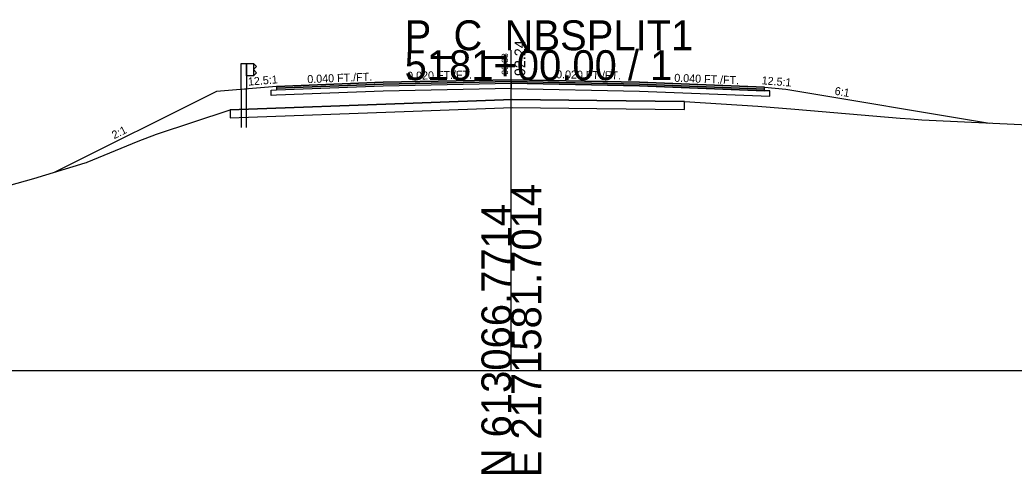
# Model space of a CAD drawing. Extents: x -26 to 1303, y -3010 to 12038.
# Drawn here: x 103.9 to 197.1, y 3990.3 to 4032.8 of the extents above; entities that cross this region are included whole.
import ezdxf

# ---------------------------------------------------------------- set-up
doc = ezdxf.new("R2010")
doc.units = 0
for name, color, linetype in [('RD_GPK_XS_Cell', 7, 'Continuous'), ('RD_PD_Final_TrvlWay', 7, 'Continuous'), ('RD_XS_Base', 7, 'Continuous'), ('RD_XS_ExGround', 7, 'Continuous'), ('RD_XS_ExPaveRet', 7, 'Continuous'), ('RD_XS_GR', 7, 'Continuous'), ('RD_XS_Greenside', 7, 'Continuous'), ('RD_XS_Pave', 7, 'Continuous'), ('RD_XS_PaveOvlay_CP', 7, 'Continuous'), ('RD_XS_TieSlope', 7, 'Continuous'), ('RD_XS_TX_Elev_EX', 7, 'Continuous'), ('RD_XS_TX_Elev_PR', 7, 'Continuous'), ('RD_XS_TX_ShdSlope', 7, 'Continuous'), ('RD_XS_TX_Slope', 7, 'Continuous')]:
    doc.layers.add(name, color=color, linetype=linetype)

msp = doc.modelspace()

# ---------------------------------------------------------------- linework, layer by layer
at = {"layer": 'RD_GPK_XS_Cell'}
for p, q in [((150, 4000), (150, 4030)), ((0, 4000), (150, 4000)), ((150, 4000), (300, 4000))]:
    msp.add_line(p, q, dxfattribs=at)
at = {"layer": 'RD_PD_Final_TrvlWay'}
for p, q in [((125.167, 4026.37), (124.667, 4026.33)), ((124.667, 4026.33), (124.667, 4022.765)), ((125.167, 4022.765), (125.167, 4026.37))]:
    msp.add_line(p, q, dxfattribs=at)
at = {"layer": 'RD_XS_Base'}
for p, q in [((127.5, 4026.259), (128, 4026.279)), ((127.5, 4025.759), (127.5, 4026.259)), ((127.5, 4026.259), (127.5, 4026.259)), ((128, 4026.279), (138, 4026.679)), ((128, 4026.279), (128, 4026.279)), ((138, 4026.679), (150, 4026.919)), ((138, 4026.679), (138, 4026.679)), ((150, 4026.419), (138, 4026.179)), ((150, 4026.919), (150, 4027.078)), ((150, 4027.078), (150, 4026.419)), ((150, 4026.919), (150, 4026.419)), ((162, 4026.679), (150, 4026.919)), ((150, 4026.919), (150, 4026.919)), ((150, 4026.419), (150, 4026.419)), ((150, 4026.419), (150, 4026.419)), ((150, 4026.419), (162, 4026.179)), ((173.73, 4026.21), (162, 4026.679)), ((164, 4026.599), (164, 4026.599)), ((128, 4025.779), (127.5, 4025.759)), ((127.5, 4025.759), (127.5, 4025.759)), ((127.5, 4025.759), (127.5, 4025.759)), ((138, 4026.179), (128, 4025.779)), ((128, 4025.779), (128, 4025.779)), ((138, 4026.179), (138, 4026.179)), ((162, 4026.179), (174.23, 4025.69)), ((164, 4026.099), (164, 4026.099)), ((174.23, 4026.19), (173.73, 4026.21)), ((173.73, 4026.21), (173.73, 4026.21)), ((174.23, 4025.69), (174.23, 4026.19)), ((174.23, 4026.19), (174.23, 4026.19)), ((174.23, 4025.69), (174.23, 4025.69)), ((174.23, 4025.69), (174.23, 4025.69))]:
    msp.add_line(p, q, dxfattribs=at)
at = {"layer": 'RD_XS_ExGround'}
msp.add_lwpolyline([(99.745, 4016.465), (105.253, 4017.976), (110.058, 4019.449), (110.199, 4019.485), (110.247, 4019.506), (115.027, 4021.491), (116.735, 4022.133), (123.656, 4024.42), (140.788, 4025.039), (150.122, 4025.383), (158.017, 4025.282), (166.242, 4025.191), (173.101, 4024.77), (176.558, 4024.471), (186.456, 4023.653), (187.417, 4023.59), (188.464, 4023.497), (189.144, 4023.466), (200.442, 4022.913)], dxfattribs=at)
at = {"layer": 'RD_XS_ExPaveRet'}
msp.add_line((166.242, 4025.191), (158.017, 4025.282), dxfattribs=at)
for points in [[(158.017, 4025.282), (150.122, 4025.383), (150.122, 4025.383), (150.122, 4025.383), (140.788, 4025.039), (140.788, 4025.039), (123.656, 4024.42), (123.656, 4024.42), (123.656, 4023.67), (140.788, 4024.289), (140.788, 4024.289), (150.122, 4024.633), (150.122, 4024.633), (150.122, 4024.633), (158.017, 4024.532), (158.017, 4024.532), (166.242, 4024.441), (166.242, 4025.191), (166.242, 4025.191), (158.017, 4025.282), (158.017, 4025.282)], [(158.017, 4025.282), (150.122, 4025.383), (140.788, 4025.039), (123.656, 4024.42)], [(123.656, 4024.42), (123.656, 4023.67), (140.788, 4024.289), (150.122, 4024.633), (158.017, 4024.532), (166.242, 4024.441), (166.242, 4025.191)]]:
    msp.add_lwpolyline(points, dxfattribs=at)
at = {"layer": 'RD_XS_GR'}
for points in [[(125.167, 4028.765), (125.167, 4026.37), (124.667, 4026.33), (124.667, 4028.765), (124.917, 4028.765), (125.167, 4028.765)], [(125.834, 4028.765), (125.834, 4027.599), (125.167, 4027.599), (125.167, 4028.765), (125.834, 4028.765)], [(126.105, 4028.474), (125.834, 4028.765), (125.834, 4027.599), (125.834, 4027.599), (125.834, 4027.599), (126.105, 4027.89), (126.105, 4027.89), (125.834, 4028.182), (125.834, 4028.182), (126.105, 4028.474), (126.105, 4028.474)]]:
    msp.add_lwpolyline(points, dxfattribs=at)
at = {"layer": 'RD_XS_Greenside'}
for p, q in [((175.73, 4026.368), (194.823, 4023.186)), ((122.355, 4026.145), (107.228, 4018.582))]:
    msp.add_line(p, q, dxfattribs=at)
at = {"layer": 'RD_XS_Pave'}
for p, q in [((150, 4027.237), (138, 4026.997)), ((162, 4026.997), (150, 4027.237)), ((138, 4026.997), (128, 4026.597)), ((138, 4026.838), (128, 4026.438)), ((128, 4026.438), (138, 4026.838)), ((128, 4026.279), (138, 4026.679)), ((128, 4026.597), (128, 4026.597)), ((128, 4026.597), (128, 4026.438)), ((128, 4026.438), (128, 4026.438)), ((128, 4026.438), (128, 4026.279)), ((128, 4026.438), (128, 4026.438)), ((128, 4026.438), (128, 4026.438)), ((128, 4026.279), (128, 4026.279)), ((128, 4026.279), (128, 4026.279)), ((150, 4027.078), (138, 4026.838)), ((138, 4026.838), (150, 4027.078)), ((138, 4026.997), (138, 4026.997)), ((138, 4026.679), (150, 4026.919)), ((138, 4026.838), (138, 4026.838)), ((138, 4026.838), (138, 4026.838)), ((138, 4026.679), (138, 4026.679)), ((150, 4026.919), (150, 4027.078)), ((150, 4027.078), (162, 4026.838)), ((162, 4026.838), (150, 4027.078)), ((150, 4027.078), (150, 4026.919)), ((150, 4026.919), (150, 4026.919)), ((150, 4026.919), (150, 4026.919)), ((150, 4026.919), (162, 4026.679)), ((173.73, 4026.528), (162, 4026.997)), ((162, 4026.838), (173.73, 4026.369)), ((173.73, 4026.369), (162, 4026.838)), ((162, 4026.679), (173.73, 4026.21)), ((164, 4026.917), (164, 4026.917)), ((164, 4026.758), (164, 4026.758)), ((164, 4026.758), (164, 4026.758)), ((164, 4026.599), (164, 4026.599)), ((173.73, 4026.369), (173.73, 4026.528)), ((173.73, 4026.528), (173.73, 4026.528)), ((173.73, 4026.369), (173.73, 4026.369)), ((173.73, 4026.369), (173.73, 4026.369)), ((173.73, 4026.21), (173.73, 4026.369)), ((173.73, 4026.369), (173.73, 4026.369)), ((173.73, 4026.21), (173.73, 4026.21)), ((173.73, 4026.21), (173.73, 4026.21))]:
    msp.add_line(p, q, dxfattribs=at)
at = {"layer": 'RD_XS_PaveOvlay_CP'}
for p, q in [((138, 4026.997), (150, 4027.237)), ((150, 4027.237), (162, 4026.997)), ((128, 4026.597), (138, 4026.997)), ((162, 4026.997), (173.73, 4026.528))]:
    msp.add_line(p, q, dxfattribs=at)
at = {"layer": 'RD_XS_TieSlope'}
for p, q in [((128, 4026.597), (122.355, 4026.145)), ((173.73, 4026.528), (175.73, 4026.368))]:
    msp.add_line(p, q, dxfattribs=at)

# ---------------------------------------------------------------- texts
at = {"layer": 'RD_GPK_XS_Cell'}
for s, p in [('P_C_NBSPLIT1', (140, 4030)), ('5181+00.00 / 1', (140, 4027.2))]:
    msp.add_text(s, height=2.8, dxfattribs=at).set_placement(p)
for s, p in [('E 2171581.7014', (152.8, 3990)), ('N 613066.7714', (150, 3990))]:
    msp.add_text(s, height=2.8, rotation=90, dxfattribs=at).set_placement(p)
at = {"layer": 'RD_XS_TX_Elev_EX'}
msp.add_text('90.38', height=0.6, rotation=90, dxfattribs=at).set_placement((149.692, 4027.71))
at = {"layer": 'RD_XS_TX_Elev_PR'}
msp.add_text('92.24', height=1, rotation=90, dxfattribs=at).set_placement((151.301, 4027.585))
at = {"layer": 'RD_XS_TX_ShdSlope'}
for rotation, p in [(4.57392, (125.35, 4026.684)), (355.42608, (173.441, 4026.818))]:
    msp.add_text('12.5:1', height=0.75, rotation=rotation, dxfattribs=at).set_placement(p)
at = {"layer": 'RD_XS_TX_Slope'}
for s, rotation, p in [('0.020 FT./FT.', 1.14576, (140.248, 4027.227)), ('0.020 FT./FT.', 358.85424, (154.191, 4027.38)), ('0.040 FT./FT.', 2.29061, (130.895, 4026.915)), ('0.040 FT./FT.', 357.70939, (165.262, 4027.052)), ('6:1', 350.53768, (180.26, 4025.846)), ('2:1', 26.56505, (112.789, 4021.663))]:
    msp.add_text(s, height=0.75, rotation=rotation, dxfattribs=at).set_placement(p)

doc.saveas('drawing.dxf')
